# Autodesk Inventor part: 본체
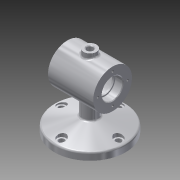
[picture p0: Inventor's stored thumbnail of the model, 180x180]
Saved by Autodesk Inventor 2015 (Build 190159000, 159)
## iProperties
Created: 2018-12
Part Number: 본체
Material: 알루미늄 6061
Document SubType Name: Modeling
Designer: now
Density: 2.7 g/cm^3
Appearance: 알루미늄 - 평지
Mass: 685.089 g
Surface Area: 555.482 cm^2
Volume: 253.737 cm^3
Author: now
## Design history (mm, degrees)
sketch "스케치1"
  geometry: C1 r 30 at (0, 0); 1 further point
  constraints: 1 centre point, 1 coincident
  dimensions: "d0" = 60 diameter of C1
extrude "돌출1" new body sketch "스케치1" stored distance "d1" = 70; taper "d2" = 0 deg
sketch "스케치2"
  geometry: L1 (35, 30)-(35, -30) reference; L2 (35, -30)-(-35, -30) reference; L3 (-35, -30)-(-35, 30) reference; L4 (-35, 30)-(35, 30) reference; L5 (35, -30)-(35, 30) reference; L6 (35, 0)-(23, 0); L7 (23, 0)-(23, 15.7); L8 (23.3, 16)-(35, 16); L9 (35, 16)-(35, 0); A1 r 0.3 centre (23.3, 15.7) between (23.3, 16) and (23, 15.7); 2 further points
  constraints: 8 end point, 2 parallel, 2 point on circle, 2 point on line, 2 tangent, 1 centre point, 1 horizontal, 1 midpoint, 1 perpendicular
  dimensions: "d3" = 16 distance of L6.end point (23, 16); "d4" = 12 distance of L6.start L6.end; "d6" = 0.3 radius of A1
revolve "회전1" sketch "스케치2" stored, may be unused: angle "d5" = 90 deg
sketch "스케치3"
  geometry: L1 (23.3, -16)-(35, -16) reference; L2 (35, -16)-(35, -30) reference; L3 (35, -30)-(-35, -30) reference; L4 (-35, -30)-(-35, 30) reference; L5 (-35, 30)-(35, 30) reference; L6 (35, 30)-(35, 16) reference; L7 (35, 16)-(23.3, 16) reference; L8 (23, 15.7)-(23, -15.7) reference; L9 (23, 15.7)-(23, -15.7) reference; L10 (23, 0)-(20, 0); L11 (20, 0)-(20, 14); L12 (20, 14)-(23, 14); L13 (23, 14)-(23, 0); A1 r 0.3 centre (23.3, 15.7) between (23.3, 16) and (23, 15.7) reference; A2 r 0.3 centre (23.3, -15.7) between (23, -15.7) and (23.3, -16) reference; 1 further point
  constraints: 8 end point, 2 parallel, 1 horizontal, 1 midpoint, 1 perpendicular
  dimensions: "d7" = 3 distance of L10.start L10.end; "d8" = 14 distance of L10.end L11.end
revolve "회전2" sketch "스케치3" stored, may be unused: angle "d9" = 90 deg
sketch "스케치4"
  geometry: L1 (23.3, -16)-(35, -16) reference; L2 (35, -16)-(35, -30) reference; L3 (35, -30)-(-35, -30) reference; L4 (-35, -30)-(-35, 30) reference; L5 (-35, 30)-(35, 30) reference; L6 (35, 30)-(35, 16) reference; L7 (35, 16)-(23.3, 16) reference; L8 (23, 15.7)-(23, 14) reference; L9 (23, 14)-(20, 14) reference; L10 (20, 14)-(20, -14) reference; L11 (20, -14)-(23, -14) reference; L12 (23, -14)-(23, -15.7) reference; L13 (20, 0)-(-20, 0); L14 (-20, 0)-(-20, 22); L15 (-17, 25)-(17, 25); L16 (20, 22)-(20, 0); A1 r 0.3 centre (23.3, 15.7) between (23.3, 16) and (23, 15.7) reference; A2 r 0.3 centre (23.3, -15.7) between (23, -15.7) and (23.3, -16) reference; A3 r 3 centre (17, 22) between (20, 22) and (17, 25); A4 r 3 centre (-17, 22) between (-17, 25) and (-20, 22); 2 further points
  constraints: 8 end point, 4 point on circle, 4 tangent, 2 centre point, 2 parallel, 2 point on line, 1 equal radius, 1 horizontal, 1 midpoint, 1 perpendicular
  dimensions: "d10" = 40 distance of L13.start L13.end; "d11" = 25 distance of L13.end point (-20, 25); "d12" = 3 radius of A3
revolve "회전3" sketch "스케치4" stored, may be unused: angle "d13" = 90 deg
sketch "스케치5"
  geometry: L1 (23.3, -16)-(35, -16) reference; L2 (35, -16)-(35, -30) reference; L3 (35, -30)-(-35, -30) reference; L4 (-35, -30)-(-35, 30) reference; L5 (-35, 30)-(35, 30) reference; L6 (35, 30)-(35, 16) reference; L7 (35, 16)-(23.3, 16) reference; L8 (23, 15.7)-(23, 14) reference; L9 (23, 14)-(20, 14) reference; L10 (20, 14)-(20, 22) reference; L11 (17, 25)-(-17, 25) reference; L12 (-20, 22)-(-20, -22) reference; L13 (-17, -25)-(17, -25) reference; L14 (20, -22)-(20, -14) reference; L15 (20, -14)-(23, -14) reference; L16 (23, -14)-(23, -15.7) reference; L17 (-20, 22)-(-20, -22) reference; L18 (-20, 0)-(-23, 0); L19 (-23, 0)-(-23, 14); L20 (-23, 14)-(-20, 14); L21 (-20, 14)-(-20, 0); A1 r 0.3 centre (23.3, 15.7) between (23.3, 16) and (23, 15.7) reference; A2 r 3 centre (17, 22) between (20, 22) and (17, 25) reference; A3 r 3 centre (-17, 22) between (-17, 25) and (-20, 22) reference; A4 r 3 centre (-17, -22) between (-20, -22) and (-17, -25) reference; A5 r 3 centre (17, -22) between (17, -25) and (20, -22) reference; A6 r 0.3 centre (23.3, -15.7) between (23, -15.7) and (23.3, -16) reference; 1 further point
  constraints: 8 end point, 2 parallel, 1 horizontal, 1 midpoint, 1 perpendicular
  dimensions: "d14" = 3 distance of L18.start L18.end; "d15" = 14 distance of L18.end L19.end
revolve "회전4" sketch "스케치5" stored, may be unused: angle "d16" = 90 deg
sketch "스케치6"
  geometry: L1 (23.3, -16)-(35, -16) reference; L2 (35, -16)-(35, -30) reference; L3 (35, -30)-(-35, -30) reference; L4 (-35, -30)-(-35, 30) reference; L5 (-35, 30)-(35, 30) reference; L6 (35, 30)-(35, 16) reference; L7 (35, 16)-(23.3, 16) reference; L8 (23, 15.7)-(23, 14) reference; L9 (23, 14)-(20, 14) reference; L10 (20, 14)-(20, 22) reference; L11 (17, 25)-(-17, 25) reference; L12 (-20, 22)-(-20, 14) reference; L13 (-20, 14)-(-23, 14) reference; L14 (-23, 14)-(-23, -14) reference; L15 (-23, -14)-(-20, -14) reference; L16 (-20, -14)-(-20, -22) reference; L17 (-17, -25)-(17, -25) reference; L18 (20, -22)-(20, -14) reference; L19 (20, -14)-(23, -14) reference; L20 (23, -14)-(23, -15.7) reference; L21 (-35, 30)-(-35, -30) reference; L22 (-23, 0)-(-35, 0); L23 (-35, 0)-(-35, 16); L24 (-35, 16)-(-23.3, 16); L25 (-23, 15.7)-(-23, 0); A1 r 0.3 centre (23.3, 15.7) between (23.3, 16) and (23, 15.7) reference; A2 r 3 centre (17, 22) between (20, 22) and (17, 25) reference; A3 r 3 centre (-17, 22) between (-17, 25) and (-20, 22) reference; A4 r 3 centre (-17, -22) between (-20, -22) and (-17, -25) reference; A5 r 3 centre (17, -22) between (17, -25) and (20, -22) reference; A6 r 0.3 centre (23.3, -15.7) between (23, -15.7) and (23.3, -16) reference; A7 r 0.3 centre (-23.3, 15.7) between (-23, 15.7) and (-23.3, 16); 2 further points
  constraints: 8 end point, 3 point on line, 2 parallel, 2 point on circle, 2 tangent, 1 centre point, 1 horizontal, 1 midpoint, 1 perpendicular
  dimensions: "d17" = 16 distance of point (-23, 16) L22.start; "d18" = 0.3 radius of A7
revolve "회전5" sketch "스케치6" stored, may be unused: angle "d19" = 90 deg
chamfer "모따기1" distance "d20" = 1; stored, may be unused: second distance "d21" = 2, angle "d22" = 45 deg
sketch "스케치7"
  geometry: C1 r 30 at (0, 0) reference; 1 further point
  constraints: 1 horizontal alignment
  dimensions: "d23" = 23 distance of point (23, 0) C1.centre
hole "구멍1" sketch "스케치7" at (23, 0) diameter "d24" = 3.242; stored, may be unused: countersink angle "d28" = 90 deg, drill point angle "d30" = 118 deg; dims "d25" = 8, "d26" = 4, "d27" = 2, "d29" = 10
node "작업 평면1"
sketch "스케치8"
  geometry: L1 (-35, 30)-(-35, -30) reference; C1 r 10 at (0, 0); 2 further points
  constraints: 1 centre point, 1 horizontal alignment, 1 midpoint
  dimensions: "d35" = 20 diameter of C1; "d36" = 35 distance from line of C1.centre L1
extrude "돌출2" join sketch "스케치8" stored distance "d37" = 70; taper "d38" = 0 deg
sketch "스케치9"
  geometry: C1 r 10 at (0, 0) reference; C2 r 5 at (0, 0)
  constraints: 1 centre point, 1 coincident
  dimensions: "d39" = 10 diameter of C2
extrude "돌출3" cut sketch "스케치9" stored distance "d40" = 70; taper "d41" = 0 deg
chamfer "모따기2" distance "d42" = 1; stored, may be unused: second distance "d43" = 2, angle "d44" = 45 deg
node "작업 평면2"
sketch "스케치10"
  geometry: C1 r 55 at (0, 0); 1 further point
  constraints: 1 centre point, 1 coincident
  dimensions: "d46" = 110 diameter of C1
extrude "돌출4" join sketch "스케치10" distance "d47" = 11; taper "d48" = 0 deg
sketch "스케치11"
  geometry: L1 (35, 17)-(34, 16) reference; L2 (34, 16)-(23.3, 16) reference; L3 (23, 15.7)-(23, 14) reference; L4 (23, 14)-(20, 14) reference; L5 (20, 14)-(20, 22) reference; L6 (17, 25)-(5, 25) reference; L7 (5, 25)-(5, 36) reference; L8 (5, 36)-(6, 37) reference; L9 (6, 37)-(10, 37) reference; L10 (10, 37)-(10, 30) reference; L11 (10, 30)-(35, 30) reference; L12 (35, 30)-(35, 24.621) reference; L13 (35, 24.621)-(25, 24.621) reference; L14 (25, 24.621)-(24.026, 23) reference; L15 (24.026, 23)-(25, 21.379) reference; L16 (25, 21.379)-(35, 21.379) reference; L17 (35, 21.379)-(35, 17) reference; L18 (-35, -17)-(-34, -16) reference; L19 (-34, -16)-(-23.3, -16) reference; L20 (-23, -15.7)-(-23, -14) reference; L21 (-23, -14)-(-20, -14) reference; L22 (-20, -14)-(-20, -22) reference; L23 (-17, -25)-(17, -25) reference; L24 (20, -22)-(20, -14) reference; L25 (20, -14)-(23, -14) reference; L26 (23, -14)-(23, -15.7) reference; L27 (23.3, -16)-(34, -16) reference; L28 (34, -16)-(35, -17) reference; L29 (35, -17)-(35, -21.379) reference; L30 (35, -21.379)-(25, -21.379) reference; L31 (25, -21.379)-(24.026, -23) reference; L32 (24.026, -23)-(25, -24.621) reference; L33 (25, -24.621)-(35, -24.621) reference; L34 (35, -24.621)-(35, -30) reference; L35 (35, -30)-(-35, -30) reference; L36 (-35, -30)-(-35, -24.621) reference; L37 (-35, -24.621)-(-25, -24.621) reference; L38 (-25, -24.621)-(-24.026, -23) reference; L39 (-24.026, -23)-(-25, -21.379) reference; L40 (-25, -21.379)-(-35, -21.379) reference; L41 (-35, -21.379)-(-35, -17) reference; L42 (-34, 16)-(-35, 17) reference; L43 (-35, 17)-(-35, 21.379) reference; L44 (-35, 21.379)-(-25, 21.379) reference; L45 (-25, 21.379)-(-24.026, 23) reference; L46 (-24.026, 23)-(-25, 24.621) reference; L47 (-25, 24.621)-(-35, 24.621) reference; L48 (-35, 24.621)-(-35, 30) reference; L49 (-35, 30)-(-10, 30) reference; L50 (-10, 30)-(-10, 37) reference; L51 (-10, 37)-(-6, 37) reference; L52 (-6, 37)-(-5, 36) reference; L53 (-5, 36)-(-5, 25) reference; L54 (-5, 25)-(-17, 25) reference; L55 (-20, 22)-(-20, 14) reference; L56 (-20, 14)-(-23, 14) reference; L57 (-23, 14)-(-23, 15.7) reference; L58 (-23.3, 16)-(-34, 16) reference; L59 (-55, -75)-(-55, -64) reference; L60 (-55, -64)-(55, -64) reference; L61 (55, -64)-(55, -75) reference; L62 (55, -75)-(-55, -75) reference; L63 (0, -64)-(0, -49.263); L64 (55, -64)-(0, -49.263); A1 r 0.3 centre (23.3, 15.7) between (23.3, 16) and (23, 15.7) reference; A2 r 3 centre (17, 22) between (20, 22) and (17, 25) reference; A3 r 0.3 centre (-23.3, -15.7) between (-23.3, -16) and (-23, -15.7) reference; A4 r 3 centre (-17, -22) between (-20, -22) and (-17, -25) reference; A5 r 3 centre (17, -22) between (17, -25) and (20, -22) reference; A6 r 0.3 centre (23.3, -15.7) between (23, -15.7) and (23.3, -16) reference; A7 r 3 centre (-17, 22) between (-17, 25) and (-20, 22) reference; A8 r 0.3 centre (-23.3, 15.7) between (-23, 15.7) and (-23.3, 16) reference; 2 further points
  constraints: 4 end point, 2 midpoint, 1 vertical alignment
  dimensions: "d50" = 75 deg angle of L64 L61
revolve "회전6" sketch "스케치11" stored, may be unused: angle "d51" = 90 deg
sketch "스케치12"
  geometry: C1 r 55 at (0, 0) reference; C2 r 12 at (0, 0)
  constraints: 1 centre point, 1 coincident
  dimensions: "d52" = 24 diameter of C2
extrude "돌출5" join sketch "스케치12" stored distance "d53" = 11; taper "d54" = 0 deg
sketch "스케치13"
  geometry: C1 r 55 at (0, 0) reference; 1 further point
  constraints: 1 horizontal alignment
  dimensions: "d55" = 44 distance of point (-44, 0) C1.centre
hole "구멍2" sketch "스케치13" at (-44, 0) diameter "d56" = 9; stored, may be unused: countersink angle "d60" = 90 deg, drill point angle "d62" = 0 deg; dims "d57" = 8, "d58" = 14, "d59" = 2, "d61" = 10
sketch "스케치14"
  geometry: C1 r 4.5 at (0, 0) reference; C2 r 7 at (0, 0); 1 further point
  constraints: 1 centre point, 1 coincident
  dimensions: "d63" = 14 diameter of C2
extrude "돌출6" cut sketch "스케치14" stored distance "d64" = 11; taper "d65" = 0 deg
fillet "모깎기1" dims "d69" = 3
fillet "모깎기2" dims "d70" = 3
node "작업 평면3"
sketch "스케치15"
  geometry: L1 (-35, 30)-(-35, -30) reference; 2 further points
  constraints: 1 other
  dimensions: "d72" = 35 distance from line of L1 point (0, 0); "d73" = 30 vertical distance of L1.start point (0, 0)
feature "엠보싱1" sketch "스케치15" dims "d1" = 70, "d74" = 0.5, "d75" = 0
sketch "스케치16"
  geometry: 1 further point
node "솔리드1"
pattern_circular "원형 패턴1" dims angle "d32" = 360 deg
mirror "대칭1"
pattern_circular "원형 패턴2" dims angle "d67" = 360 deg
node "절단 모서리 투영1"
node "절단 모서리 투영2"
node "절단 모서리 투영3"
node "절단 모서리 투영4"
node "절단 모서리 투영5"
node "절단 모서리 투영6"
other parameters: "d34" = 37, "d45" = -75, "d71" = 60.25
